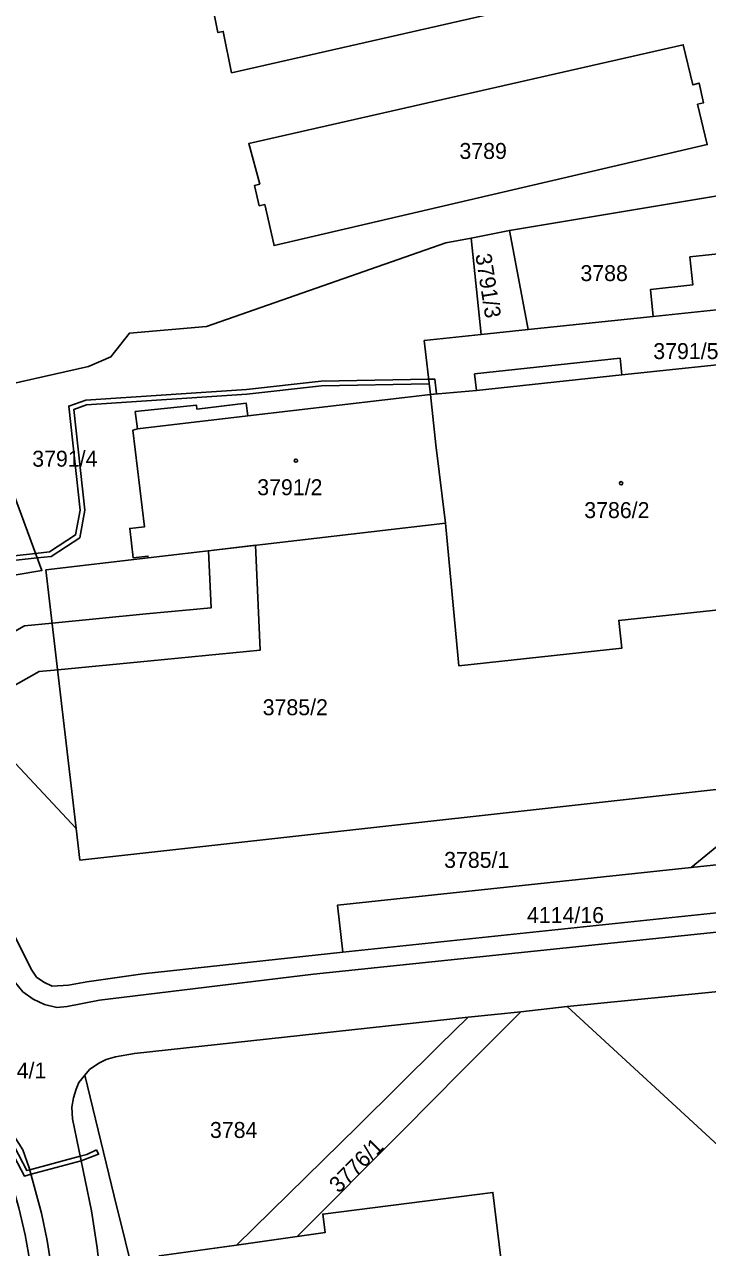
# Model space of a CAD drawing. Extents: x -869103 to -863415, y -1015889 to -1012477.
# Drawn here: x -867065.2 to -866992.3, y -1014872 to -1014741.6 of the extents above; entities that cross this region are included whole.
import ezdxf

# ---------------------------------------------------------------- set-up
doc = ezdxf.new("R2010")
doc.units = 0
for name, color, linetype in [('Hranice parcel', 7, 'Continuous'), ('Parcelní čísla', 7, 'Continuous'), ('Vnitřní kresba', 7, 'Continuous'), ('Věcná břemena k části', 7, 'Continuous'), ('Značky budov', 7, 'Continuous')]:
    doc.layers.add(name, color=color, linetype=linetype)

msp = doc.modelspace()

# ---------------------------------------------------------------- linework, layer by layer
at = {"layer": 'Hranice parcel'}
for p, q in [((-866984.95, -1014758.83), (-867013.45, -1014763.59)), ((-867017.54, -1014764.38), (-867013.45, -1014763.59)), ((-867013.45, -1014763.59), (-867011.46, -1014774.13)), ((-867017.54, -1014764.38), (-867016.45, -1014774.65)), ((-866987.31, -1014771.6), (-866998.11, -1014772.73)), ((-866998.11, -1014772.73), (-867011.46, -1014774.13)), ((-867016.45, -1014774.65), (-867022.55, -1014775.29)), ((-867011.46, -1014774.13), (-867016.45, -1014774.65)), ((-867022.55, -1014775.29), (-867021.88, -1014781.05)), ((-867020.28, -1014794.76), (-867051.97, -1014798.46)), ((-867051.97, -1014798.46), (-867062.87, -1014799.74)), ((-867062.87, -1014799.74), (-867059.64, -1014827.3)), ((-867059.64, -1014827.3), (-867069.03, -1014817.28)), ((-867059.64, -1014827.3), (-867059.24, -1014830.69)), ((-866991.34, -1014829.23), (-866994.07, -1014831.47)), ((-866985.78, -1014835.71), (-867031.22, -1014840.49)), ((-866979.07, -1014843.48), (-867007.28, -1014846.3)), ((-867007.28, -1014846.3), (-867012.25, -1014846.84)), ((-866990.28, -1014861.94), (-867007.28, -1014846.3)), ((-867017.85, -1014847.44), (-867020.93, -1014850.45)), ((-867018.57, -1014853.18), (-867012.25, -1014846.84)), ((-867017.85, -1014847.44), (-867012.25, -1014846.84)), ((-867055.58, -1014866.52), (-867058.72, -1014853.62)), ((-867042.56, -1014871.71), (-867036.09, -1014870.8))]:
    msp.add_line(p, q, dxfattribs=at)
for points in [[(-867004.18, -1014726.4), (-867038.13, -1014734.18), (-867038.45, -1014732.77), (-867042.78, -1014733.79), (-867042.47, -1014735.17), (-867045.3, -1014735.82), (-867044.4, -1014740.23), (-867044.98, -1014740.35), (-867044.54, -1014742.48), (-867043.97, -1014742.36), (-867043.07, -1014746.77), (-867001.89, -1014737.4)], [(-867040.15, -1014760.95), (-867039.54, -1014760.81), (-867038.55, -1014765.19), (-866992.35, -1014754.42), (-866993.38, -1014750.12), (-866992.74, -1014749.96), (-866993.21, -1014747.87), (-866993.88, -1014748.06), (-866994.91, -1014743.77), (-867041.25, -1014754.31), (-867040.07, -1014758.65), (-867040.65, -1014758.78), (-867040.15, -1014760.95)], [(-867095.93, -1014760.16), (-867097.7, -1014761.11), (-867099.4, -1014762.15), (-867100.85, -1014763.6), (-867101.87, -1014765.34), (-867102.38, -1014766.87), (-867102.6, -1014768.68), (-867102.41, -1014770.24), (-867101.71, -1014772.17), (-867092.75, -1014790.31), (-867085.14, -1014805.25), (-867075.49, -1014824.98), (-867066.25, -1014843.6), (-867065.35, -1014844.71), (-867064.22, -1014845.5), (-867063.01, -1014846.08), (-867061.7, -1014846.38), (-867060.61, -1014846.29), (-867057.17, -1014845.63), (-867034.35, -1014842.85), (-866982.15, -1014837.42)], [(-867073.86, -1014801.59), (-867063.3, -1014799.81), (-867070.34, -1014780.76), (-867058.32, -1014778.06), (-867055.94, -1014777.05), (-867053.97, -1014774.52), (-867045.76, -1014773.82), (-867020.23, -1014764.9), (-867017.54, -1014764.38)], [(-866994.23, -1014766.4), (-866993.91, -1014769.38), (-866998.42, -1014769.87), (-866998.11, -1014772.73)], [(-866984, -1014766.51), (-866991.09, -1014767.37), (-866991.2, -1014766.07), (-866994.23, -1014766.4)], [(-866983.26, -1014781.38), (-866986.11, -1014781.69), (-866986.56, -1014777.38), (-867001.45, -1014778.97), (-867001.65, -1014777.2), (-867017.16, -1014778.86), (-867016.96, -1014780.63), (-867021.88, -1014781.05)], [(-867021.88, -1014781.05), (-867041.35, -1014783.33), (-867041.51, -1014781.99), (-867046.77, -1014782.61), (-867046.82, -1014782.18), (-867053.34, -1014782.88), (-867053.12, -1014784.71), (-867053.59, -1014784.86), (-867052.35, -1014795.15), (-867053.94, -1014795.33), (-867053.58, -1014798.46), (-867051.99, -1014798.28), (-867051.97, -1014798.46)], [(-867021.88, -1014781.05), (-867021.28, -1014786.42), (-867020.28, -1014794.76)], [(-866981.12, -1014800.99), (-866984.01, -1014801.18), (-866983.79, -1014803.21), (-867001.8, -1014805.13), (-867001.48, -1014808.11), (-867018.83, -1014809.96), (-867020.28, -1014794.76)], [(-867059.24, -1014830.69), (-866978.92, -1014821.79), (-866979.34, -1014817.82)], [(-867031.22, -1014840.49), (-867052.55, -1014842.82), (-867058.5, -1014843.66), (-867060.47, -1014844.03), (-867062.19, -1014844.13), (-867063.08, -1014843.71), (-867063.88, -1014843.15), (-867064.45, -1014842.31), (-867074.36, -1014822.39)], [(-866985.78, -1014835.71), (-866986.32, -1014830.65), (-866994.07, -1014831.47)], [(-866994.07, -1014831.47), (-867031.78, -1014835.47), (-867031.22, -1014840.49)], [(-867058.72, -1014853.62), (-867058.21, -1014853), (-867057.24, -1014852.34), (-867056.46, -1014851.94), (-867055.44, -1014851.67), (-867053.43, -1014851.29), (-867017.85, -1014847.44)], [(-867020.93, -1014850.45), (-867029.63, -1014859.05), (-867042.56, -1014871.71)], [(-867058.38, -1014909.1), (-867052.36, -1014907.64), (-867056.28, -1014881.95), (-867056.92, -1014876.38), (-867057.4, -1014872.02), (-867058.02, -1014868.06), (-867060.03, -1014858.25), (-867060.12, -1014857.01), (-867059.92, -1014856.01), (-867059.66, -1014855.1), (-867059.35, -1014854.4), (-867058.72, -1014853.62)], [(-867036.09, -1014870.8), (-867024.78, -1014859.47), (-867018.57, -1014853.18)], [(-867106.86, -1014885.3), (-867108.46, -1014882.93), (-867109.14, -1014880.58), (-867108.97, -1014878.75), (-867108.32, -1014877.06), (-867107.15, -1014875.66), (-867106.1, -1014874.99), (-867072.93, -1014857.78), (-867072.05, -1014857.37), (-867071.21, -1014857.19), (-867070.4, -1014857.43), (-867069.59, -1014857.74), (-867068.42, -1014858.25), (-867067.58, -1014858.79), (-867066.43, -1014859.83), (-867065.35, -1014861.56), (-867064.65, -1014863.47), (-867063.34, -1014868.3), (-867062.74, -1014871.22), (-867062.29, -1014874.19), (-867061.24, -1014883.64), (-867061.38, -1014885.65), (-867058.38, -1014909.1)], [(-867061.57, -1014897.59), (-867061.98, -1014894.41), (-867063.47, -1014883.52), (-867064.45, -1014874.58), (-867064.73, -1014872.6), (-867065.1, -1014870.64), (-867065.77, -1014867.75), (-867066.85, -1014863.87), (-867067.39, -1014862.46), (-867067.86, -1014861.59), (-867068.53, -1014860.84), (-867069.32, -1014860.23), (-867070.2, -1014859.74), (-867071.02, -1014859.52), (-867071.98, -1014859.71), (-867089.1, -1014868.59)], [(-867050.94, -1014885.67), (-867052.02, -1014880.97), (-867055.58, -1014866.52)], [(-867036.09, -1014870.8), (-867033.11, -1014870.38), (-867033.36, -1014868.42), (-867015.21, -1014866.1), (-867011.31, -1014898.21)], [(-867049.36, -1014884.09), (-867050.79, -1014872.86), (-867042.56, -1014871.71)]]:
    msp.add_lwpolyline(points, dxfattribs=at)
at = {"layer": 'Vnitřní kresba'}
for p, q in [((-867001.45, -1014778.97), (-867016.96, -1014780.63)), ((-867041.35, -1014783.33), (-867053.12, -1014784.71))]:
    msp.add_line(p, q, dxfattribs=at)
at = {"layer": 'Věcná břemena k části'}
for points in [[(-867072.73, -1014799.46), (-867063.79, -1014798.47), (-867062.31, -1014798.31), (-867059.25, -1014796.32), (-867058.71, -1014793.4), (-867059.89, -1014782.64), (-867058.53, -1014782.15), (-867041.44, -1014781.02), (-867033.48, -1014780.13), (-867022.01, -1014779.91), (-867021.88, -1014781.05), (-867021.21, -1014780.99), (-867021.41, -1014779.41), (-867022.07, -1014779.42), (-867033.52, -1014779.63), (-867041.48, -1014780.52), (-867058.63, -1014781.65), (-867060.43, -1014782.3), (-867059.21, -1014793.38), (-867059.71, -1014796.02), (-867062.49, -1014797.83), (-867063.97, -1014797.99), (-867072.81, -1014798.96)], [(-867068.02, -1014813.07), (-867063.61, -1014810.59), (-867061.62, -1014810.4), (-867051.69, -1014809.43), (-867040.02, -1014808.3), (-867040.54, -1014797.13), (-867045.52, -1014797.71), (-867045.24, -1014803.78), (-867052.17, -1014804.45), (-867062.2, -1014805.42), (-867065.15, -1014805.71), (-867070.5, -1014808.73)], [(-867066.61, -1014861.59), (-867065.16, -1014864.36), (-867064.46, -1014864.17), (-867059.11, -1014862.74), (-867057.25, -1014862.03), (-867057.47, -1014861.57)], [(-867057.47, -1014861.57), (-867058.5, -1014862.05), (-867059.21, -1014862.24), (-867064.59, -1014863.7), (-867064.9, -1014863.78), (-867066.23, -1014861.25)]]:
    msp.add_lwpolyline(points, dxfattribs=at)
at = {"layer": 'Značky budov'}
for centre in [(-867036.22, -1014788.11), (-867001.55, -1014790.51)]:
    msp.add_circle(centre, 0.175, dxfattribs=at)

# ---------------------------------------------------------------- texts
at = {"layer": 'Parcelní čísla'}
for s, p in [('3789', (-867018.78, -1014755.95)), ('3788', (-867005.88, -1014768.97)), ('3791/5', (-866998.11, -1014777.28)), ('3791/4', (-867064.33, -1014788.75)), ('3791/2', (-867040.34, -1014791.79)), ('3786/2', (-867005.47, -1014794.23)), ('3785/2', (-867039.76, -1014815.24)), ('3785/1', (-867020.41, -1014831.51)), ('4114/16', (-867011.58, -1014837.39)), ('4114/1', (-867069.78, -1014853.96)), ('3784', (-867045.38, -1014860.3))]:
    msp.add_text(s, height=1.7, dxfattribs=at).set_placement(p)
for s, rotation, p in [('3791/3', 279, (-867017.09, -1014766.15)), ('3776/1', 45, (-867031.65, -1014866.26))]:
    msp.add_text(s, height=1.7, rotation=rotation, dxfattribs=at).set_placement(p)

doc.saveas('drawing.dxf')
